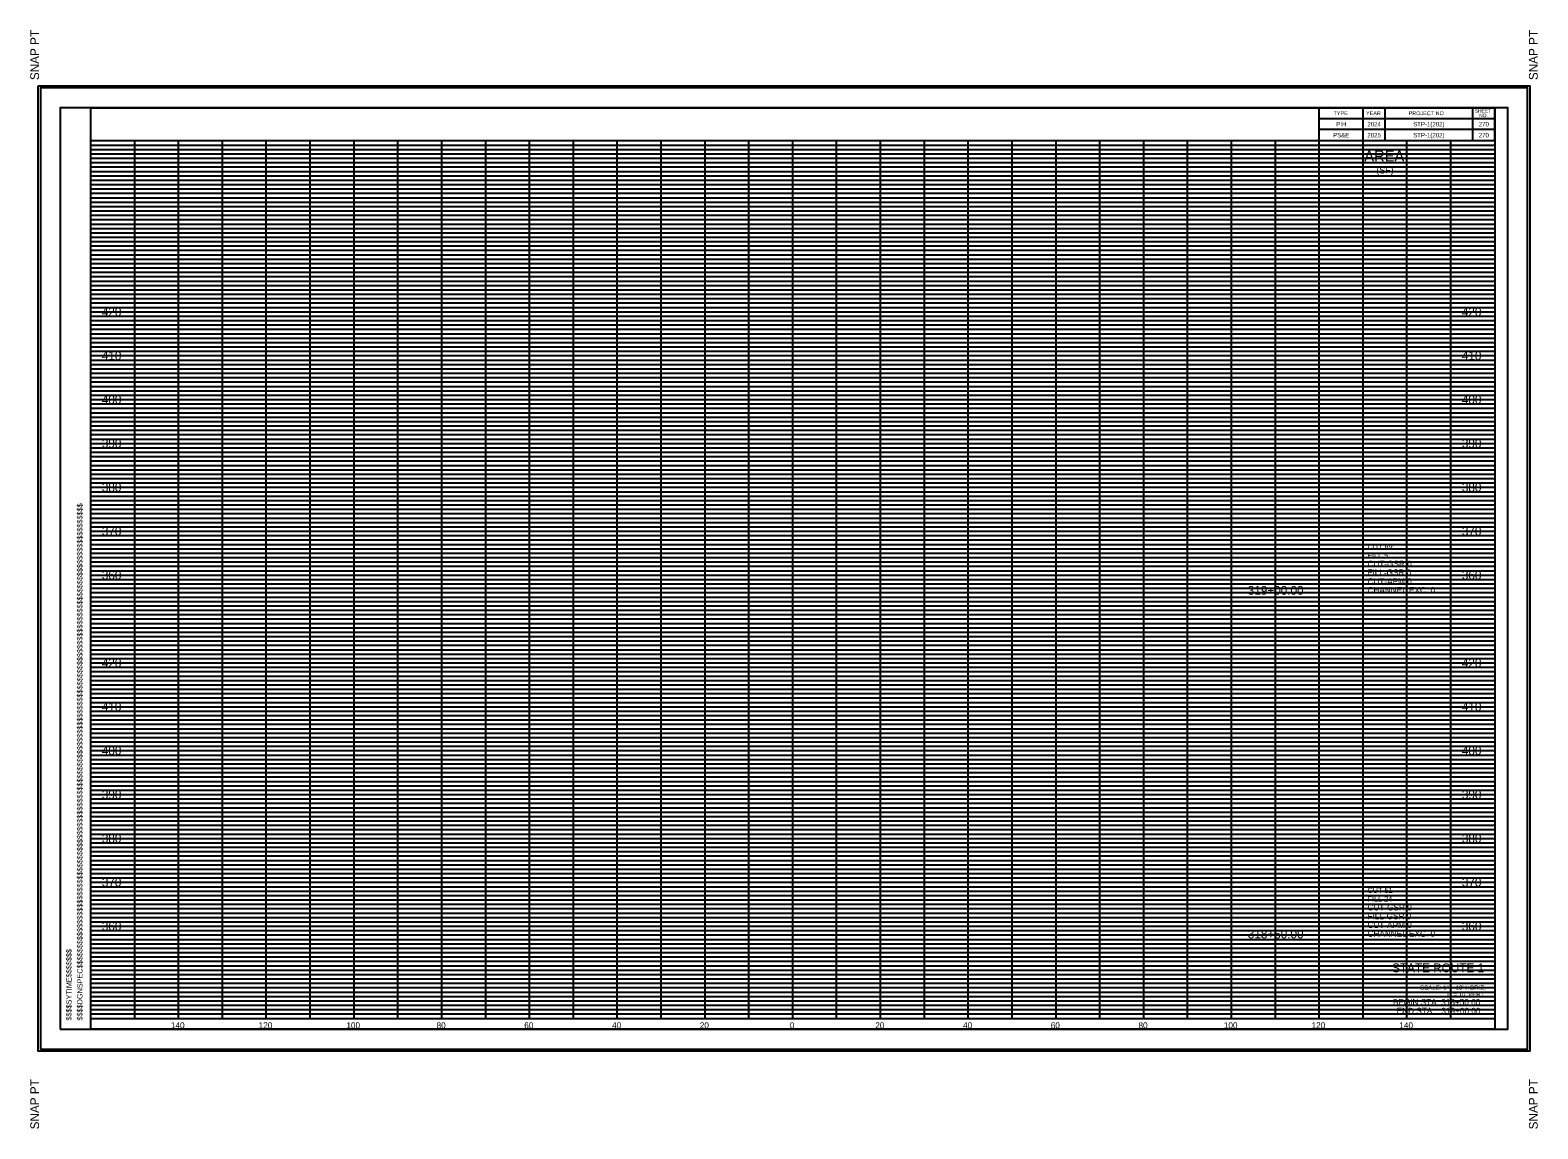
# Model space of a CAD drawing. Extents: x -200 to 23470, y -200 to 2389.
# Drawn here: x 22756.2 to 23099.8, y 1494.8 to 1745.2 of the extents above; entities that cross this region are included whole.
import ezdxf

# ---------------------------------------------------------------- set-up
doc = ezdxf.new("R2010")
doc.units = 0
for name, color, linetype in [('Default', 7, 'Continuous'), ('DESIGN - SCRATCH - User 1', 7, 'Continuous'), ('DESIGN - SHEET - Corner Text', 7, 'Continuous'), ('DESIGN - SHEET - Light Grid', 7, 'Continuous'), ('DESIGN - SHEET - Linework', 7, 'Continuous'), ('DESIGN - SHEET - Plot Shape', 7, 'Continuous'), ('DESIGN - TYPICAL - Text', 7, 'Continuous')]:
    doc.layers.add(name, color=color, linetype=linetype)

# ---------------------------------------------------------------- blocks, each defined once
blk = doc.blocks.new('XSTSHT')
at = {"layer": 'DESIGN - SCRATCH - User 1'}
for p, q in [((28.5, 20.375), (28.5, 20.375)), ((29.25, 20.375), (29.25, 20.375)), ((30.5, 20.375), (30.5, 20.375)), ((31.75, 20.375), (31.75, 20.375)), ((28.5, 20.125), (28.5, 20.125)), ((29.25, 20.125), (29.25, 20.125)), ((30.5, 20.125), (30.5, 20.125)), ((31.75, 20.125), (31.75, 20.125)), ((0, 0), (0, 0))]:
    blk.add_line(p, q, dxfattribs=at)
at = {"layer": 'DESIGN - SHEET - Light Grid'}
for p, q in [((0, 19.9), (32, 19.9)), ((0, 19.8), (32, 19.8)), ((0, 19.7), (32, 19.7)), ((0, 19.6), (32, 19.6)), ((0, 19.5), (32, 19.5)), ((0, 19.4), (32, 19.4)), ((0, 19.3), (32, 19.3)), ((0, 19.2), (32, 19.2)), ((0, 19.1), (32, 19.1)), ((0, 18.9), (32, 18.9)), ((0, 18.8), (32, 18.8)), ((0, 18.7), (32, 18.7)), ((0, 18.6), (32, 18.6)), ((0, 18.5), (32, 18.5)), ((0, 18.4), (32, 18.4)), ((0, 18.3), (32, 18.3)), ((0, 18.2), (32, 18.2)), ((0, 18.1), (32, 18.1)), ((0, 17.9), (32, 17.9)), ((0, 17.8), (32, 17.8)), ((0, 17.7), (32, 17.7)), ((0, 17.6), (32, 17.6)), ((0, 17.5), (32, 17.5)), ((0, 17.4), (32, 17.4)), ((0, 17.3), (32, 17.3)), ((0, 17.2), (32, 17.2)), ((0, 17.1), (32, 17.1)), ((0, 16.9), (32, 16.9)), ((0, 16.8), (32, 16.8)), ((0, 16.7), (32, 16.7)), ((0, 16.6), (32, 16.6)), ((0, 16.5), (32, 16.5)), ((0, 16.4), (32, 16.4)), ((0, 16.3), (32, 16.3)), ((0, 16.2), (32, 16.2)), ((0, 16.1), (32, 16.1)), ((0, 15.9), (32, 15.9)), ((0, 15.8), (32, 15.8)), ((0, 15.7), (32, 15.7)), ((0, 15.6), (32, 15.6)), ((0, 15.5), (32, 15.5)), ((0, 15.4), (32, 15.4)), ((0, 15.3), (32, 15.3)), ((0, 15.2), (32, 15.2)), ((0, 15.1), (32, 15.1)), ((0, 14.9), (32, 14.9)), ((0, 14.8), (32, 14.8)), ((0, 14.7), (32, 14.7)), ((0, 14.6), (32, 14.6)), ((0, 14.5), (32, 14.5)), ((0, 14.4), (32, 14.4)), ((0, 14.3), (32, 14.3)), ((0, 14.2), (32, 14.2)), ((0, 14.1), (32, 14.1)), ((0, 13.9), (32, 13.9)), ((0, 13.8), (32, 13.8)), ((0, 13.7), (32, 13.7)), ((0, 13.6), (32, 13.6)), ((0, 13.5), (32, 13.5)), ((0, 13.4), (32, 13.4)), ((0, 13.3), (32, 13.3)), ((0, 13.2), (32, 13.2)), ((0, 13.1), (32, 13.1)), ((0, 12.9), (32, 12.9)), ((0, 12.8), (32, 12.8)), ((0, 12.7), (32, 12.7)), ((0, 12.6), (32, 12.6)), ((0, 12.5), (32, 12.5)), ((0, 12.4), (32, 12.4)), ((0, 12.3), (32, 12.3)), ((0, 12.2), (32, 12.2)), ((0, 12.1), (32, 12.1)), ((0, 11.9), (32, 11.9)), ((0, 11.8), (32, 11.8)), ((0, 11.7), (32, 11.7)), ((0, 11.6), (32, 11.6)), ((0, 11.5), (32, 11.5)), ((0, 11.4), (32, 11.4)), ((0, 11.3), (32, 11.3)), ((0, 11.2), (32, 11.2)), ((0, 11.1), (32, 11.1)), ((0, 10.9), (32, 10.9)), ((0, 10.8), (32, 10.8)), ((0, 10.7), (32, 10.7)), ((0, 10.6), (32, 10.6)), ((0, 10.5), (32, 10.5)), ((0, 10.4), (32, 10.4)), ((0, 10.3), (32, 10.3)), ((0, 10.2), (32, 10.2)), ((0, 10.1), (32, 10.1)), ((0, 9.9), (32, 9.9)), ((0, 9.8), (32, 9.8)), ((0, 9.7), (32, 9.7)), ((0, 9.6), (32, 9.6)), ((0, 9.5), (32, 9.5)), ((0, 9.4), (32, 9.4)), ((0, 9.3), (32, 9.3)), ((0, 9.2), (32, 9.2)), ((0, 9.1), (32, 9.1)), ((0, 8.9), (32, 8.9)), ((0, 8.8), (32, 8.8)), ((0, 8.7), (32, 8.7)), ((0, 8.6), (32, 8.6)), ((0, 8.5), (32, 8.5)), ((0, 8.4), (32, 8.4)), ((0, 8.3), (32, 8.3)), ((0, 8.2), (32, 8.2)), ((0, 8.1), (32, 8.1)), ((0, 7.9), (32, 7.9)), ((0, 7.8), (32, 7.8)), ((0, 7.7), (32, 7.7)), ((0, 7.6), (32, 7.6)), ((0, 7.5), (32, 7.5)), ((0, 7.4), (32, 7.4)), ((0, 7.3), (32, 7.3)), ((0, 7.2), (32, 7.2)), ((0, 7.1), (32, 7.1)), ((0, 6.9), (32, 6.9)), ((0, 6.8), (32, 6.8)), ((0, 6.7), (32, 6.7)), ((0, 6.6), (32, 6.6)), ((0, 6.5), (32, 6.5)), ((0, 6.4), (32, 6.4)), ((0, 6.3), (32, 6.3)), ((0, 6.2), (32, 6.2)), ((0, 6.1), (32, 6.1)), ((0, 5.9), (32, 5.9)), ((0, 5.8), (32, 5.8)), ((0, 5.7), (32, 5.7)), ((0, 5.6), (32, 5.6)), ((0, 5.5), (32, 5.5)), ((0, 5.4), (32, 5.4)), ((0, 5.3), (32, 5.3)), ((0, 5.2), (32, 5.2)), ((0, 5.1), (32, 5.1)), ((0, 4.9), (32, 4.9)), ((0, 4.8), (32, 4.8)), ((0, 4.7), (32, 4.7)), ((0, 4.6), (32, 4.6)), ((0, 4.5), (32, 4.5)), ((0, 4.4), (32, 4.4)), ((0, 4.3), (32, 4.3)), ((0, 4.2), (32, 4.2)), ((0, 4.1), (32, 4.1)), ((0, 3.9), (32, 3.9)), ((0, 3.8), (32, 3.8)), ((0, 3.7), (32, 3.7)), ((0, 3.6), (32, 3.6)), ((0, 3.5), (32, 3.5)), ((0, 3.4), (32, 3.4)), ((0, 3.3), (32, 3.3)), ((0, 3.2), (32, 3.2)), ((0, 3.1), (32, 3.1)), ((0, 2.9), (32, 2.9)), ((0, 2.8), (32, 2.8)), ((0, 2.7), (32, 2.7)), ((0, 2.6), (32, 2.6)), ((0, 2.5), (32, 2.5)), ((0, 2.4), (32, 2.4)), ((0, 2.3), (32, 2.3)), ((0, 2.2), (32, 2.2)), ((0, 2.1), (32, 2.1)), ((0, 1.9), (32, 1.9)), ((0, 1.8), (32, 1.8)), ((0, 1.7), (32, 1.7)), ((0, 1.6), (32, 1.6)), ((0, 1.5), (32, 1.5)), ((0, 1.4), (32, 1.4)), ((0, 1.3), (32, 1.3)), ((0, 1.2), (32, 1.2)), ((0, 1.1), (32, 1.1)), ((0, 0.9), (32, 0.9)), ((0, 0.8), (32, 0.8)), ((0, 0.7), (32, 0.7)), ((0, 0.6), (32, 0.6)), ((0, 0.5), (32, 0.5)), ((0, 0.4), (32, 0.4)), ((0, 0.3), (32, 0.3)), ((0, 0.2), (32, 0.2)), ((0, 0.1), (32, 0.1))]:
    blk.add_line(p, q, dxfattribs=at)
at = {"layer": 'DESIGN - SHEET - Linework'}
for p, q in [((32, 20.75), (28, 20.75)), ((28, 20), (28, 20.75)), ((29, 20), (29, 20.75)), ((29.5, 20), (29.5, 20.75)), ((31.5, 20), (31.5, 20.75)), ((32, 20), (32, 20.75)), ((32, 20.5), (28, 20.5)), ((0, 20), (32, 20)), ((1, 0), (1, 20)), ((2, 0), (2, 20)), ((3, 0), (3, 20)), ((4, 0), (4, 20)), ((5, 0), (5, 20)), ((6, 0), (6, 20)), ((7, 0), (7, 20)), ((8, 0), (8, 20)), ((9, 0), (9, 20)), ((10, 0), (10, 20)), ((11, 0), (11, 20)), ((12, 0), (12, 20)), ((13, 0), (13, 20)), ((14, 0), (14, 20)), ((15, 0), (15, 20)), ((16, 0), (16, 20)), ((17, 0), (17, 20)), ((18, 0), (18, 20)), ((19, 0), (19, 20)), ((20, 0), (20, 20)), ((21, 0), (21, 20)), ((22, 0), (22, 20)), ((23, 0), (23, 20)), ((24, 0), (24, 20)), ((25, 0), (25, 20)), ((26, 0), (26, 20)), ((27, 0), (27, 20)), ((32, 20.25), (28, 20.25)), ((28, 0), (28, 20)), ((29, 0), (29, 20)), ((30, 0), (30, 20)), ((31, 0), (31, 20)), ((0, 19), (32, 19)), ((0, 18), (32, 18)), ((0, 17), (32, 17)), ((0, 16), (32, 16)), ((0, 15), (32, 15)), ((0, 14), (32, 14)), ((0, 13), (32, 13)), ((0, 12), (32, 12)), ((0, 11), (32, 11)), ((0, 10), (32, 10)), ((0, 9), (32, 9)), ((0, 8), (32, 8)), ((0, 7), (32, 7)), ((0, 6), (32, 6)), ((0, 5), (32, 5)), ((0, 4), (32, 4)), ((0, 3), (32, 3)), ((0, 2), (32, 2)), ((0, 1), (32, 1)), ((0, 0), (32, 0))]:
    blk.add_line(p, q, dxfattribs=at)
for points in [[(-1.2, 21.25), (32.8, 21.25), (32.8, -0.75), (-1.2, -0.75)], [(0, 20.75), (32, 20.75), (32, -0.25), (0, -0.25)]]:
    blk.add_lwpolyline(points, close=True, dxfattribs=at)
at = {"layer": 'DESIGN - SHEET - Corner Text'}
for s, height, p in [('  SNAP PT', 0.2, (-1.18, 21.23)), ('  SNAP PT', 0.2, (32.98, 21.23)), ('$$$$DGNSPEC$$$$$$$$$$$$$$$$$$$$$$$$$$$$$$$$$$$$$$$$$$$$$$$$$$$$$$$$$$$$$$$$$$$$$$$$$$$$$$$$$$$$$$$$$$$$$$$$$$$$$$$$$$$$$$$$$$$', 0.12, (-0.19, -0.05)), ('$$$$SYTIME$$$$$$$', 0.12, (-0.44, -0.05)), ('SNAP PT  ', 0.2, (-1.18, -2.53)), ('SNAP PT  ', 0.2, (32.98, -2.53))]:
    blk.add_text(s, height=height, rotation=90, dxfattribs=at).set_placement(p)
at = {"layer": 'DESIGN - SHEET - Light Grid'}
for s, height, p in [('TYPE', 0.09, (28.326, 20.58)), ('YEAR', 0.09, (29.066, 20.58)), ('PROJECT NO.', 0.09, (30.038, 20.58)), ('SHEET', 0.08, (31.547, 20.635)), ('NO.', 0.08, (31.647, 20.535))]:
    blk.add_text(s, height=height, dxfattribs=at).set_placement(p)

msp = doc.modelspace()

# ---------------------------------------------------------------- linework, layer by layer
at = {"layer": 'DESIGN - SHEET - Plot Shape'}
for points in [[(22758.5, 1513), (23097.5, 1513), (23097.5, 1732), (22758.5, 1732)], [(22763, 1517.5), (23093, 1517.5), (23093, 1727.5), (22763, 1727.5)]]:
    msp.add_lwpolyline(points, close=True, dxfattribs=at)

# ---------------------------------------------------------------- block references
at = {"layer": 'DESIGN - SHEET - Plot Shape', "xscale": 10, "yscale": 10}
msp.add_blockref('XSTSHT', (22770, 1520), dxfattribs=at)

# ---------------------------------------------------------------- texts
at = {"layer": 'Default'}
for s, height, p in [('     420     ', 2, (22768.79, 1680)), ('     420     ', 2, (23078.79, 1680)), ('     410     ', 2, (22768.79, 1670)), ('     410     ', 2, (23078.79, 1670)), ('     400     ', 2, (22768.79, 1660)), ('     400     ', 2, (23078.79, 1660)), ('     390     ', 2, (22768.79, 1650)), ('     390     ', 2, (23078.79, 1650)), ('     380     ', 2, (22768.79, 1640)), ('     380     ', 2, (23078.79, 1640)), ('     370     ', 2, (22768.79, 1630)), ('     370     ', 2, (23078.79, 1630)), ('     360     ', 2, (22768.79, 1620)), ('     360     ', 2, (23078.79, 1620)), ('     319+00.00     ', 2, (23030, 1616.52)), ('     420     ', 2, (22768.79, 1600)), ('     420     ', 2, (23078.79, 1600)), ('     410     ', 2, (22768.79, 1590)), ('     410     ', 2, (23078.79, 1590)), ('     400     ', 2, (22768.79, 1580)), ('     400     ', 2, (23078.79, 1580)), ('     390     ', 2, (22768.79, 1570)), ('     390     ', 2, (23078.79, 1570)), ('     380     ', 2, (22768.79, 1560)), ('     380     ', 2, (23078.79, 1560)), ('     370     ', 2, (22768.79, 1550)), ('     370     ', 2, (23078.79, 1550)), ('     360     ', 2, (22768.79, 1540)), ('     318+50.00     ', 2, (23030, 1538.21)), ('     360     ', 2, (23078.79, 1540)), ('     140     ', 1.4, (22785.65, 1517.7)), ('     120     ', 1.4, (22805.65, 1517.7)), ('     100     ', 1.4, (22825.65, 1517.7)), ('     80     ', 1.4, (22846.2, 1517.7)), ('     60     ', 1.4, (22866.2, 1517.7)), ('     40     ', 1.4, (22886.2, 1517.7)), ('     20     ', 1.4, (22906.2, 1517.7)), ('     0     ', 1.4, (22926.74, 1517.7)), ('     0     ', 1.4, (22926.74, 1517.7)), ('     20     ', 1.4, (22946.2, 1517.7)), ('     40     ', 1.4, (22966.2, 1517.7)), ('     60     ', 1.4, (22986.2, 1517.7)), ('     80     ', 1.4, (23006.2, 1517.7)), ('     100     ', 1.4, (23025.65, 1517.7)), ('     120     ', 1.4, (23045.65, 1517.7)), ('     140     ', 1.4, (23065.65, 1517.7))]:
    msp.add_text(s, height=height, dxfattribs=at).set_placement(p)
at = {"layer": 'DESIGN - SHEET - Corner Text'}
for s, height, p in [('PS&E', 1, (23053.17, 1720.75)), ('PIH', 1, (23053.89, 1723.25)), ('2025', 1, (23060.97, 1720.75)), ('2024', 1, (23060.98, 1723.25)), ('STP-1(202)', 1, (23071.42, 1723.25)), ('STP-1(202)', 1, (23071.42, 1720.75)), ('270', 1, (23086.37, 1723.25)), ('270', 1, (23086.37, 1720.75)), ('STATE ROUTE 1', 2, (23066.62, 1530.5)), ('SCALE: 1" = 10\' HORIZ.', 1, (23072.96, 1526.5)), ('1" = 10\' VERT.', 1, (23078.93, 1525)), ('BEGIN STA. 318+50.00', 1.4, (23066.78, 1523)), ('END STA.   319+00.00', 1.4, (23067.65, 1521))]:
    msp.add_text(s, height=height, dxfattribs=at).set_placement(p)
at = {"layer": 'DESIGN - TYPICAL - Text'}
for s, height, p in [('AREA', 2.5, (23060.27, 1715.26)), ('(SF)', 1.5, (23063.03, 1712.51)), ('CUT 69', 1.2, (23061, 1626.89)), ('FILL 5', 1.2, (23061, 1624.89)), ('CUT-GSR 0', 1.4, (23061, 1622.89)), ('FILL-GSR 0', 1.4, (23061, 1620.89)), ('CUT-APM 0', 1.4, (23061, 1618.89)), ('CHANNEL EXC. 0', 1.4, (23061, 1616.89)), ('CUT 51', 1.2, (23061, 1548.58)), ('FILL 24', 1.2, (23061, 1546.58)), ('CUT-GSR 0', 1.4, (23061, 1544.58)), ('FILL-GSR 0', 1.4, (23061, 1542.58)), ('CUT-APM 0', 1.4, (23061, 1540.58)), ('CHANNEL EXC. 0', 1.4, (23061, 1538.58))]:
    msp.add_text(s, height=height, dxfattribs=at).set_placement(p)

doc.saveas('drawing.dxf')
